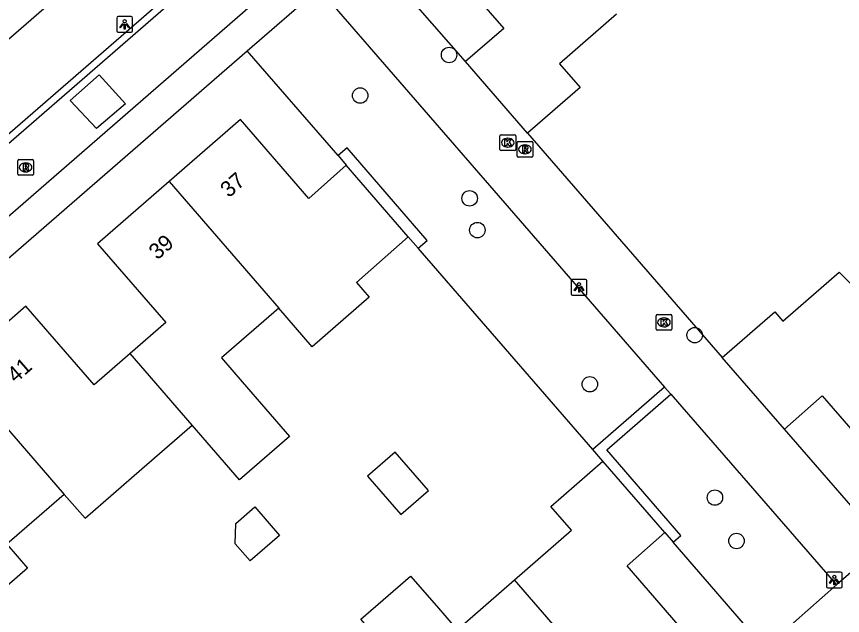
# Model space of a CAD drawing. Extents: x 155888 to 156864, y 383882 to 384671.
# Drawn here: x 156227.5 to 156279.9, y 384195.3 to 384233.2 of the extents above; entities that cross this region are included whole.
import ezdxf

# ---------------------------------------------------------------- set-up
doc = ezdxf.new("R2010")
doc.units = 0
for name, color, linetype in [('IMGEO_Boom', 7, 'Continuous'), ('IMGEO_Groenvoorziening', 7, 'Continuous'), ('IMGEO_Kolk', 7, 'Continuous'), ('IMGEO_Lichtpunt', 7, 'Continuous'), ('IMGEO_Pand', 7, 'Continuous'), ('IMGEO_Pand_nummerreeks', 7, 'Continuous'), ('IMGEO_Rijbaan_lokaal_gesloten', 7, 'Continuous'), ('IMGEO_Rijbaan_lokaal_open', 7, 'Continuous'), ('IMGEO_Rioolput', 7, 'Continuous'), ('IMGEO_Voetpad_open', 7, 'Continuous')]:
    doc.layers.add(name, color=color, linetype=linetype)

msp = doc.modelspace()

# ---------------------------------------------------------------- linework, layer by layer
at = {"layer": 'IMGEO_Boom'}
for centre in [(156254.937, 384230.779), (156249.306, 384228.208), (156256.238, 384221.7), (156256.728, 384219.688), (156270.498, 384213.038), (156263.857, 384209.928), (156271.778, 384202.752), (156273.145, 384200.005)]:
    msp.add_circle(centre, 0.489, dxfattribs=at)
at = {"layer": 'IMGEO_Groenvoorziening'}
for points in [[(156247.902, 384224.402), (156242.149, 384231.047)], [(156264.04, 384205.796), (156252.985, 384218.538)], [(156274.939, 384193.214), (156269.134, 384199.929)]]:
    msp.add_lwpolyline(points, dxfattribs=at)
at = {"layer": 'IMGEO_Kolk'}
for p, q in [((156258.156, 384224.801), (156258.156, 384225.653)), ((156258.231, 384225.727), (156259.083, 384225.727)), ((156259.157, 384225.653), (156259.157, 384224.801)), ((156258.644, 384225.507), (156258.669, 384225.507)), ((156259.083, 384224.727), (156258.231, 384224.727)), ((156258.667, 384224.947), (156258.642, 384224.947)), ((156268.05, 384213.418), (156268.05, 384214.27)), ((156268.125, 384214.344), (156268.977, 384214.344)), ((156268.538, 384214.124), (156268.563, 384214.124)), ((156269.051, 384214.27), (156269.051, 384213.418)), ((156268.977, 384213.344), (156268.125, 384213.344)), ((156268.561, 384213.564), (156268.536, 384213.564))]:
    msp.add_line(p, q, dxfattribs=at)
for points in [[(156258.156, 384224.801), (156258.156, 384225.653)], [(156258.231, 384225.727), (156259.083, 384225.727)], [(156259.157, 384225.653), (156259.157, 384224.801)], [(156258.477, 384225.427), (156258.6, 384225.427), (156258.6, 384225.276), (156258.73, 384225.427), (156258.894, 384225.427), (156258.748, 384225.276), (156258.901, 384225.027), (156258.749, 384225.027), (156258.664, 384225.191), (156258.6, 384225.124), (156258.6, 384225.027), (156258.477, 384225.027), (156258.477, 384225.427)], [(156259.083, 384224.727), (156258.231, 384224.727)], [(156268.05, 384213.418), (156268.05, 384214.27)], [(156268.125, 384214.344), (156268.977, 384214.344)], [(156269.051, 384214.27), (156269.051, 384213.418)], [(156268.371, 384214.044), (156268.494, 384214.044), (156268.494, 384213.893), (156268.624, 384214.044), (156268.788, 384214.044), (156268.642, 384213.893), (156268.795, 384213.644), (156268.643, 384213.644), (156268.558, 384213.808), (156268.494, 384213.741), (156268.494, 384213.644), (156268.371, 384213.644), (156268.371, 384214.044)], [(156268.977, 384213.344), (156268.125, 384213.344)]]:
    msp.add_lwpolyline(points, dxfattribs=at)
for centre, start, end in [((156258.233, 384225.651), 91.552, 178.448), ((156258.233, 384225.651), 91.552, 178.448), ((156259.081, 384225.651), 1.552, 88.448), ((156259.081, 384225.651), 1.552, 88.448), ((156258.233, 384224.803), 181.552, 268.448), ((156258.233, 384224.803), 181.552, 268.448), ((156259.081, 384224.803), 271.552, 358.448), ((156259.081, 384224.803), 271.552, 358.448), ((156268.127, 384214.268), 91.552, 178.448), ((156268.127, 384214.268), 91.552, 178.448), ((156268.975, 384214.268), 1.552, 88.448), ((156268.975, 384214.268), 1.552, 88.448), ((156268.127, 384213.42), 181.552, 268.448), ((156268.127, 384213.42), 181.552, 268.448), ((156268.975, 384213.42), 271.552, 358.448), ((156268.975, 384213.42), 271.552, 358.448)]:
    msp.add_arc(centre, 0.0765, start, end, dxfattribs=at)
for centre, major_axis, ratio, start_param, end_param in [((156258.643, 384225.227), (-0.387, 0.002), 0.722429, 4.712389, 7.853982), ((156258.668, 384225.227), (-0.39, 0.002), 0.717154, 1.570796, 4.712389), ((156268.537, 384213.844), (-0.387, 0.002), 0.722429, 4.712389, 7.853982), ((156268.562, 384213.844), (-0.39, 0.002), 0.717154, 1.570796, 4.712389)]:
    msp.add_ellipse(centre, major_axis=major_axis, ratio=ratio, start_param=start_param, end_param=end_param, dxfattribs=at)
at = {"layer": 'IMGEO_Lichtpunt'}
for p, q in [((156233.882, 384233.116), (156233.882, 384232.309)), ((156233.882, 384233.116), (156233.882, 384232.309)), ((156234.784, 384233.211), (156233.976, 384233.211)), ((156234.784, 384233.211), (156233.976, 384233.211)), ((156234.878, 384232.309), (156234.878, 384233.116)), ((156234.878, 384232.309), (156234.878, 384233.116)), ((156233.976, 384232.215), (156234.784, 384232.215)), ((156233.976, 384232.215), (156234.784, 384232.215)), ((156262.671, 384216.467), (156262.671, 384215.66)), ((156262.671, 384216.467), (156262.671, 384215.66)), ((156263.573, 384216.562), (156262.765, 384216.562)), ((156263.573, 384216.562), (156262.765, 384216.562)), ((156263.667, 384215.66), (156263.667, 384216.467)), ((156263.667, 384215.66), (156263.667, 384216.467)), ((156262.765, 384215.566), (156263.573, 384215.566)), ((156262.765, 384215.566), (156263.573, 384215.566)), ((156278.843, 384197.938), (156278.843, 384197.131)), ((156278.843, 384197.938), (156278.843, 384197.131)), ((156279.745, 384198.033), (156278.937, 384198.033)), ((156279.745, 384198.033), (156278.937, 384198.033)), ((156279.839, 384197.131), (156279.839, 384197.938)), ((156279.839, 384197.131), (156279.839, 384197.938)), ((156278.937, 384197.037), (156279.745, 384197.037)), ((156278.937, 384197.037), (156279.745, 384197.037))]:
    msp.add_line(p, q, dxfattribs=at)
for points in [[(156234.256, 384232.78), (156234.295, 384232.752), (156234.107, 384232.49), (156234.069, 384232.517), (156234.256, 384232.78)], [(156234.358, 384232.732), (156234.405, 384232.732), (156234.405, 384232.41), (156234.358, 384232.41), (156234.358, 384232.732)], [(156234.468, 384232.752), (156234.506, 384232.779), (156234.693, 384232.517), (156234.654, 384232.489), (156234.468, 384232.752)], [(156263.045, 384216.131), (156263.084, 384216.103), (156262.896, 384215.841), (156262.858, 384215.868), (156263.045, 384216.131)], [(156263.147, 384216.083), (156263.194, 384216.083), (156263.194, 384215.761), (156263.147, 384215.761), (156263.147, 384216.083)], [(156263.257, 384216.103), (156263.295, 384216.13), (156263.482, 384215.868), (156263.443, 384215.84), (156263.257, 384216.103)], [(156279.217, 384197.602), (156279.256, 384197.574), (156279.068, 384197.312), (156279.03, 384197.339), (156279.217, 384197.602)], [(156279.319, 384197.554), (156279.366, 384197.554), (156279.366, 384197.232), (156279.319, 384197.232), (156279.319, 384197.554)], [(156279.429, 384197.574), (156279.467, 384197.601), (156279.654, 384197.339), (156279.615, 384197.311), (156279.429, 384197.574)]]:
    msp.add_lwpolyline(points, dxfattribs=at)
for centre in [(156234.381, 384232.914), (156263.17, 384216.265), (156279.342, 384197.736)]:
    msp.add_circle(centre, 0.0994, dxfattribs=at)
for centre, start, end in [((156233.976, 384233.116), 90, 180), ((156233.976, 384233.116), 90, 180), ((156234.784, 384233.116), 0, 90), ((156234.784, 384233.116), 0, 90), ((156233.976, 384232.309), 180, 270), ((156233.976, 384232.309), 180, 270), ((156234.784, 384232.309), 270, 0), ((156234.784, 384232.309), 270, 360), ((156262.765, 384216.467), 90, 180), ((156262.765, 384216.467), 90, 180), ((156263.573, 384216.467), 0, 90), ((156263.573, 384216.467), 0, 90), ((156262.765, 384215.66), 180, 270), ((156262.765, 384215.66), 180, 270), ((156263.573, 384215.66), 270, 0), ((156263.573, 384215.66), 270, 360), ((156278.937, 384197.938), 90, 180), ((156278.937, 384197.938), 90, 180), ((156279.745, 384197.938), 0, 90), ((156279.745, 384197.938), 0, 90), ((156278.937, 384197.131), 180, 270), ((156278.937, 384197.131), 180, 270), ((156279.745, 384197.131), 270, 0), ((156279.745, 384197.131), 270, 360)]:
    msp.add_arc(centre, 0.0946, start, end, dxfattribs=at)
at = {"layer": 'IMGEO_Pand'}
for points in [[(156258.604, 384241.375), (156254.07, 384237.439), (156258.397, 384232.456), (156255.981, 384230.358)], [(156265.545, 384233.366), (156261.925, 384230.222), (156263.236, 384228.712), (156259.915, 384225.828)], [(156259.915, 384225.828), (156255.981, 384230.358)], [(156248.425, 384223.797), (156246.046, 384221.697), (156241.72, 384226.682), (156237.206, 384222.761)], [(156252.353, 384219.266), (156248.425, 384223.797)], [(156237.206, 384222.761), (156232.662, 384218.815), (156236.988, 384213.83), (156234.738, 384211.877)], [(156237.206, 384222.761), (156244.142, 384214.747)], [(156252.353, 384219.266), (156249.062, 384216.372), (156249.878, 384215.433), (156246.259, 384212.301), (156244.142, 384214.747)], [(156272.239, 384211.613), (156275.567, 384214.507), (156276.077, 384213.921), (156279.655, 384217.032), (156280.518, 384216.162)], [(156234.738, 384211.877), (156232.451, 384209.892), (156228.125, 384214.877), (156223.613, 384210.955)], [(156244.142, 384214.747), (156240.508, 384211.593), (156241.817, 384210.083), (156244.82, 384206.619), (156241.66, 384203.88), (156238.659, 384207.342)], [(156238.659, 384207.342), (156234.738, 384211.877)], [(156276.178, 384207.086), (156272.239, 384211.613)], [(156223.613, 384210.955), (156230.56, 384202.956)], [(156276.178, 384207.086), (156278.574, 384209.202), (156282.907, 384204.214), (156287.446, 384208.161)], [(156230.56, 384202.956), (156231.87, 384201.448), (156235.479, 384204.581), (156238.659, 384207.342)], [(156251.875, 384201.672), (156253.642, 384203.208), (156251.53, 384205.638), (156249.762, 384204.102), (156251.875, 384201.672)], [(156259.083, 384197.542), (156262.698, 384200.682), (156261.386, 384202.191), (156264.683, 384205.055)], [(156268.611, 384200.534), (156264.683, 384205.055)], [(156230.56, 384202.956), (156226.925, 384199.801), (156228.235, 384198.292), (156225.107, 384195.576)], [(156241.393, 384199.827), (156241.417, 384201.114), (156242.622, 384202.159), (156244.193, 384200.35), (156242.337, 384198.739), (156241.393, 384199.827)], [(156266.029, 384189.524), (156270.536, 384193.453), (156266.216, 384198.436), (156268.611, 384200.534)], [(156250.976, 384193.148), (156249.352, 384195.049), (156252.49, 384197.776), (156254.131, 384195.889), (156255.443, 384194.38), (156259.083, 384197.542)], [(156266.029, 384189.524), (156259.083, 384197.542)]]:
    msp.add_lwpolyline(points, dxfattribs=at)
at = {"layer": 'IMGEO_Rijbaan_lokaal_gesloten'}
for points in [[(156291.303, 384281.083), (156255.539, 384250), (156246.06, 384241.762), (156243.102, 384239.116), (156204.848, 384205.921), (156197.157, 384199.948), (156195.594, 384198.757), (156195.167, 384198.429)], [(156289.497, 384274.681), (156289.299, 384274.644), (156289.1, 384274.566), (156260.888, 384250), (156246.061, 384237.089), (156208.721, 384204.654)]]:
    msp.add_lwpolyline(points, dxfattribs=at)
at = {"layer": 'IMGEO_Rijbaan_lokaal_open'}
for points in [[(156242.8, 384239.463), (156204.556, 384206.277), (156196.854, 384200.295)], [(156234.437, 384227.683), (156232.598, 384226.116), (156230.932, 384227.901), (156232.757, 384229.53), (156234.437, 384227.683)]]:
    msp.add_lwpolyline(points, dxfattribs=at)
at = {"layer": 'IMGEO_Rioolput'}
for p, q in [((156259.245, 384224.38), (156259.245, 384225.232)), ((156259.32, 384225.306), (156260.172, 384225.306)), ((156260.246, 384225.232), (156260.246, 384224.38)), ((156259.733, 384225.086), (156259.758, 384225.086)), ((156227.609, 384223.232), (156227.609, 384224.084)), ((156227.684, 384224.158), (156228.536, 384224.158)), ((156228.61, 384224.084), (156228.61, 384223.232)), ((156260.172, 384224.306), (156259.32, 384224.306)), ((156259.756, 384224.526), (156259.731, 384224.526)), ((156228.097, 384223.938), (156228.122, 384223.938)), ((156228.536, 384223.158), (156227.684, 384223.158)), ((156228.12, 384223.378), (156228.095, 384223.378))]:
    msp.add_line(p, q, dxfattribs=at)
for points in [[(156259.245, 384224.38), (156259.245, 384225.232)], [(156259.32, 384225.306), (156260.172, 384225.306)], [(156260.246, 384225.232), (156260.246, 384224.38)], [(156259.834, 384225.004), (156259.582, 384225.006), (156259.582, 384224.606)], [(156259.582, 384224.606), (156259.706, 384224.606), (156259.706, 384224.768), (156259.717, 384224.768)], [(156259.76, 384224.925), (156259.706, 384224.925), (156259.706, 384224.844)], [(156259.706, 384224.844), (156259.758, 384224.844)], [(156259.764, 384224.739), (156259.835, 384224.606), (156259.975, 384224.606), (156259.91, 384224.732)], [(156227.609, 384223.232), (156227.609, 384224.084)], [(156227.684, 384224.158), (156228.536, 384224.158)], [(156228.61, 384224.084), (156228.61, 384223.232)], [(156260.172, 384224.306), (156259.32, 384224.306)], [(156228.198, 384223.856), (156227.946, 384223.858), (156227.946, 384223.458)], [(156227.946, 384223.458), (156228.07, 384223.458), (156228.07, 384223.62), (156228.081, 384223.62)], [(156228.124, 384223.777), (156228.07, 384223.777), (156228.07, 384223.696)], [(156228.07, 384223.696), (156228.122, 384223.696)], [(156228.128, 384223.591), (156228.199, 384223.458), (156228.339, 384223.458), (156228.274, 384223.584)], [(156228.536, 384223.158), (156227.684, 384223.158)]]:
    msp.add_lwpolyline(points, dxfattribs=at)
for centre, radius, start, end in [((156259.322, 384225.23), 0.0765, 91.552, 178.448), ((156259.322, 384225.23), 0.0765, 91.552, 178.448), ((156260.17, 384225.23), 0.0765, 1.552, 88.448), ((156260.17, 384225.23), 0.0765, 1.552, 88.448), ((156259.716, 384224.715), 0.0533, 26.0293, 88.6989), ((156259.742, 384225.033), 0.19, 274.7715, 282.9687), ((156259.766, 384224.829), 0.0964, 77.0061, 93.1865), ((156259.78, 384224.886), 0.0378, 276.6634, 79.6772), ((156259.833, 384224.894), 0.109, 350.3612, 89.416), ((156259.831, 384224.894), 0.112, 277.5842, 350.9817), ((156259.815, 384224.679), 0.108, 29.5134, 73.7905), ((156227.686, 384224.082), 0.0765, 91.552, 178.448), ((156227.686, 384224.082), 0.0765, 91.552, 178.448), ((156228.534, 384224.082), 0.0765, 1.552, 88.448), ((156228.534, 384224.082), 0.0765, 1.552, 88.448), ((156259.322, 384224.382), 0.0765, 181.552, 268.448), ((156259.322, 384224.382), 0.0765, 181.552, 268.448), ((156260.17, 384224.382), 0.0765, 271.552, 358.448), ((156260.17, 384224.382), 0.0765, 271.552, 358.448), ((156228.08, 384223.567), 0.0533, 26.0293, 88.6989), ((156228.106, 384223.885), 0.19, 274.7715, 282.9687), ((156228.13, 384223.681), 0.0964, 77.0061, 93.1865), ((156228.144, 384223.738), 0.0378, 276.6634, 79.6772), ((156228.197, 384223.746), 0.109, 350.3612, 89.416), ((156228.195, 384223.746), 0.112, 277.5842, 350.9817), ((156228.179, 384223.531), 0.108, 29.5134, 73.7905), ((156227.686, 384223.234), 0.0765, 181.552, 268.448), ((156227.686, 384223.234), 0.0765, 181.552, 268.448), ((156228.534, 384223.234), 0.0765, 271.552, 358.448), ((156228.534, 384223.234), 0.0765, 271.552, 358.448)]:
    msp.add_arc(centre, radius, start, end, dxfattribs=at)
for centre, major_axis, ratio, start_param, end_param in [((156259.732, 384224.806), (-0.387, 0.002), 0.722429, 4.712389, 7.853982), ((156259.757, 384224.806), (-0.39, 0.002), 0.717154, 1.570796, 4.712389), ((156228.096, 384223.658), (-0.387, 0.002), 0.722429, 4.712389, 7.853982), ((156228.121, 384223.658), (-0.39, 0.002), 0.717154, 1.570796, 4.712389)]:
    msp.add_ellipse(centre, major_axis=major_axis, ratio=ratio, start_param=start_param, end_param=end_param, dxfattribs=at)
at = {"layer": 'IMGEO_Voetpad_open'}
for points in [[(156196.854, 384200.295), (156194.203, 384203.337), (156239.812, 384242.902)], [(156255.981, 384230.358), (156249.638, 384237.607)], [(156242.149, 384231.047), (156246.679, 384234.978)], [(156246.679, 384234.978), (156268.595, 384209.753)], [(156201.062, 384195.394), (156242.149, 384231.047)], [(156259.915, 384225.828), (156272.239, 384211.613)], [(156252.985, 384218.538), (156253.555, 384219.032), (156248.477, 384224.9), (156247.902, 384224.402)], [(156247.902, 384224.402), (156248.425, 384223.797)], [(156252.985, 384218.538), (156252.353, 384219.266)], [(156268.595, 384209.753), (156264.04, 384205.796)], [(156268.595, 384209.753), (156268.988, 384209.3)], [(156269.134, 384199.929), (156269.623, 384200.353), (156264.921, 384205.766), (156268.988, 384209.3)], [(156268.988, 384209.3), (156279.482, 384197.222)], [(156282.504, 384199.826), (156276.178, 384207.086)], [(156264.683, 384205.055), (156264.04, 384205.796)], [(156268.611, 384200.534), (156269.134, 384199.929)], [(156282.504, 384199.826), (156279.482, 384197.222)], [(156279.482, 384197.222), (156274.939, 384193.214)]]:
    msp.add_lwpolyline(points, dxfattribs=at)

# ---------------------------------------------------------------- texts
at = {"layer": 'IMGEO_Pand_nummerreeks'}
for s, rotation, p in [('37', 40.9722, (156240.983, 384221.698)), ('39', 40.9748, (156236.453, 384217.764)), ('41', 41.0009, (156227.473, 384209.965))]:
    msp.add_text(s, height=1, rotation=rotation, dxfattribs=at).set_placement(p)

doc.saveas('drawing.dxf')
